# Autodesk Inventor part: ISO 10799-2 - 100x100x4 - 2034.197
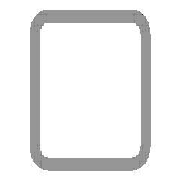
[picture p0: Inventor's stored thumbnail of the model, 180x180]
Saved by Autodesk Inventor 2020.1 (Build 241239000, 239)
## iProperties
Created: 2019-10
Part Number: ISO 10799-2 - 100x100x4 - 2034.197
Material: Stainless Steel
Description: Structural steels - Cold-formed, welded, structural hollow sections
Document SubType Name: Modeling
Standard: ISO
Designer: Synergysoft Dell02
Standard Revision: First edition 2011-09-15
Standards Organization: ISO
Language: en-US
Size Designation: 100x100x4
Categories: <MemberInstance><Categories><Category DisplayName="Structural Shapes" InternalName="089c4875-fa83-4c05-b084-43b9cc11f5ed" Mnemonic="GRDR"><CategoryParameter Dis
Stock Number: 100x100x4
Density: 8 g/cm^3
Appearance: Semi-Polished
_CCFamilyMember: 43
_CCFamilyDisplayName: ISO 10799-2 (Square) - Structural steels - Cold-formed, welded, structural hollow sections
_FrameMemberDoc: Frame Member File
_Version: 15.0.0
_GetPNFromCC: 1
G_L: 2034.197 mm
G_W: 100.000 mm
G_H: 100.000 mm
+364CA983-F1B9-4145-A582-2077FF1DB8B3+CUTDETAIL1: Cut Angle 90.00 deg
+4D97AC9F-0B52-40D7-A5FD-7CF1EC3E7FCC+CUTDETAIL2: Miter 22.50 deg
+CF5D411B-9392-4AC4-A468-38BA15CBF984+CUTDETAIL3: Miter 45.00 deg
+77BEBF81-6ADF-46E9-8364-279F4396172B+CUTDETAIL4: Cut Angle 45.00 deg
IsCustomPart: 1
Author: Synergysoft Dell02
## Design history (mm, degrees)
node "Start Plane"
node "End Plane"
sketch "Sketch"
  geometry: L1 (-50, -42)-(-50, 42); L2 (-42, 50)-(42, 50); L3 (50, 42)-(50, -42); L4 (42, -50)-(-42, -50); L5 (-42, 46)-(42, 46); L6 (46, 42)-(46, -42); L7 (42, -46)-(-42, -46); L8 (-46, -42)-(-46, 42); L9 (0, 72.32)-(0, -72.32) reference; L10 (-72.32, 0)-(72.32, 0) reference; A1 r 8 centre (-42, -42) between (-50, -42) and (-42, -50); A2 r 8 centre (42, 42) between (50, 42) and (42, 50); A3 r 8 centre (-42, 42) between (-42, 50) and (-50, 42); A4 r 8 centre (42, -42) between (42, -50) and (50, -42); A5 r 4 centre (-42, 42) between (-42, 46) and (-46, 42); A6 r 4 centre (42, 42) between (46, 42) and (42, 46); A7 r 4 centre (42, -42) between (42, -46) and (46, -42); A8 r 4 centre (-42, -42) between (-46, -42) and (-42, -46)
  constraints: 16 end point, 16 point on circle, 8 centre point, 8 tangent, 4 parallel, 3 equal radius, 2 perpendicular, 7 other
  dimensions: "d7" = 8 radius of A1 (= G_IR); "d9" = 100 distance between parallel lines of L1 L3 (= G_W); "d11" = 100 distance between parallel lines of L2 L4 (= G_H); "d12" = 4 distance between parallel lines of L3 L6 (= G_T); "d15" = 50 distance between parallel lines of L9 L3 (= 0.5 x d9); "d16" = 50 distance between parallel lines of L2 L10 (= 0.5 x d11)
extrude "Body" new body sketch "Sketch" stored distance "d3" = 2034.19724 (= G_L); taper "d4" = 0 deg
node "Driven Length"
  sketch "Sketch3"
    geometry: L1 (0, 0)-(10, 0) reference
    constraints: 2 end point, 1 horizontal
  workplane "Work Plane3"
  sketch "Sketch4"
    geometry: L1 (-2, 50)-(12, 50) reference; L2 (-2, 2084.197)-(12, 2084.197) reference
    dimensions: "d18" = 2034.19724 distance between parallel lines of L1 L2 (derived)
workplane "Work Plane4"
split "Split1"
workplane "Work Plane5"
split "Split2"
workplane "Work Plane6"
split "Split3"
workplane "Work Plane7"
split "Split4"
body "Solid1"
other parameters: "G_W" = 100 [user parameter; used in 1 equation term], "G_H" = 100 [user parameter; used in 1 equation term], "G_T" = 4 [user parameter; used in 1 equation term], "G_IR" = 8 [user parameter; used in 1 equation term], "G_L" = 2034.19724 (= d18) [user parameter; used in 1 equation term], "G_OFFSET_END" = -37.12311 [user parameter; used in 1 equation term], "d14" = 2084.19724 (= G_OFFSET_END + B_L), "B_L" = 2121.32034 [user parameter; used in 1 equation term], "d17" = 90 deg, "MAS" = 1.17 [user parameter]
